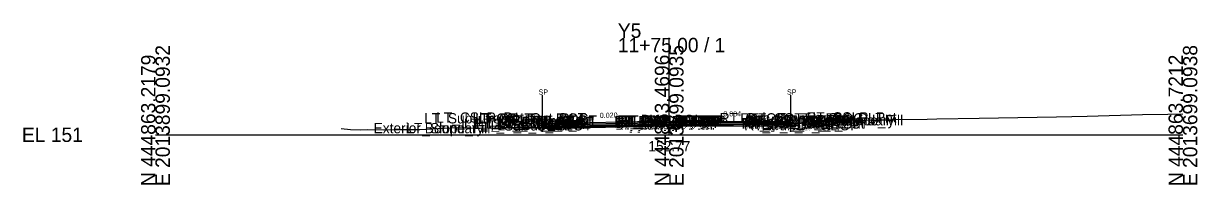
# Model space of a CAD drawing. Extents: x -26 to 203, y -10 to 4517.
# Drawn here: x -25.7 to 202.8, y 3490.3 to 3521.7 of the extents above; entities that cross this region are included whole.
import ezdxf

# ---------------------------------------------------------------- set-up
doc = ezdxf.new("R2010")
doc.units = 0
for name, color, linetype in [('Default', 7, 'Continuous'), ('Exist Cross Section Cell', 7, 'Continuous'), ('Exist XS Center Line Elevation Label', 7, 'Continuous'), ('Exist XS Ground Line', 7, 'Continuous'), ('Prop CMT Pvmt Course 1', 7, 'Continuous'), ('Prop CMT Pvmt Course 1 CG', 7, 'Continuous'), ('Prop CMT Pvmt Course 2', 7, 'Continuous'), ('Prop CMT Pvmt Course 3', 7, 'Continuous'), ('Prop CMT Pvmt Surface', 7, 'Continuous'), ('Prop CMT Shear Line', 7, 'Continuous'), ('Prop CMT Subgrade Earthwork', 7, 'Continuous'), ('Prop XS Earthwork Shape', 7, 'Continuous'), ('Prop XS SE Text', 7, 'Continuous'), ('Scratch_Level_0', 7, 'Continuous')]:
    doc.layers.add(name, color=color, linetype=linetype)

msp = doc.modelspace()

# ---------------------------------------------------------------- linework, layer by layer
at = {"layer": 'Exist Cross Section Cell'}
for p, q in [((100, 3500), (100, 3518.88)), ((0, 3500), (100, 3500)), ((100, 3500), (200, 3500))]:
    msp.add_line(p, q, dxfattribs=at)
at = {"layer": 'Exist XS Ground Line'}
msp.add_lwpolyline([(36.17, 3501.2), (37.98, 3501.05), (39.97, 3500.97), (41.27, 3501.01), (44.37, 3500.99), (46.75, 3501), (48.12, 3501.01), (49.51, 3501), (51.44, 3501.02), (58.5, 3501.4), (61.38, 3501.35), (66.68, 3501.26), (67.48, 3501.42), (71.17, 3501.42), (75.28, 3501.48), (78.99, 3501.4), (79.51, 3501.41), (86.8, 3501.57), (88.02, 3501.77), (89.34, 3501.63), (90.83, 3501.65), (100, 3501.77), (100.85, 3501.78), (101.99, 3501.79), (116.01, 3502.09), (123.64, 3502.22), (125.03, 3502.24), (125.61, 3502.24), (126.49, 3502.63), (127.48, 3502.69), (128.73, 3502.67), (131.38, 3502.66), (140.74, 3502.91), (142.43, 3502.94), (143.15, 3502.95), (150.2, 3503.07), (152.09, 3503.1), (160.32, 3503.25), (175.39, 3503.52), (181.39, 3503.63), (192.16, 3503.96), (197.08, 3504.03), (200, 3504.05)], dxfattribs=at)
at = {"layer": 'Prop CMT Pvmt Course 1'}
for points in [[(100, 3502.63), (75.24, 3502.14)], [(75.24, 3502.49), (75.24, 3502.24)], [(75.24, 3501.89), (100, 3502.38)], [(100, 3502.38), (100, 3502.63)], [(100, 3502.63), (123.6, 3502.58)], [(100, 3502.38), (100, 3502.63)], [(123.6, 3502.33), (100, 3502.38)]]:
    msp.add_lwpolyline(points, dxfattribs=at)
msp.add_lwpolyline([(100, 3502.38), (100, 3502.51), (100, 3502.51), (100, 3502.38)], close=True, dxfattribs=at)
msp.add_lwpolyline([(100, 3502.38), (100, 3502.51), (100, 3502.51), (100, 3502.38)], close=True, dxfattribs=at)
at = {"layer": 'Prop CMT Pvmt Course 1 CG'}
msp.add_lwpolyline([(75.24, 3501.58), (75.24, 3501.91)], dxfattribs=at)
at = {"layer": 'Prop CMT Pvmt Course 2'}
for points in [[(100, 3502.38), (75.24, 3501.89)], [(75.24, 3502.24), (75.24, 3501.91)], [(75.24, 3501.56), (100, 3502.05)], [(100, 3502.05), (100, 3502.38)], [(100, 3502.05), (100, 3502.38)], [(100, 3502.38), (123.6, 3502.33)], [(123.6, 3501.99), (100, 3502.05)]]:
    msp.add_lwpolyline(points, dxfattribs=at)
at = {"layer": 'Prop CMT Pvmt Course 3'}
for points in [[(100, 3502.05), (75.24, 3501.56)], [(75.24, 3501.91), (75.24, 3501.58)], [(75.24, 3501.22), (100, 3501.72)], [(100, 3501.72), (100, 3502.05)], [(100, 3502.05), (123.6, 3501.99)], [(100, 3501.72), (100, 3502.05)], [(123.6, 3501.66), (100, 3501.72)]]:
    msp.add_lwpolyline(points, dxfattribs=at)
at = {"layer": 'Prop CMT Pvmt Surface'}
for points in [[(100, 3502.63), (75.24, 3502.14)], [(100, 3502.63), (123.6, 3502.58)]]:
    msp.add_lwpolyline(points, dxfattribs=at)
at = {"layer": 'Prop CMT Shear Line'}
for p, q in [((75.24, 3507.71), (75.24, 3500.57)), ((123.6, 3507.71), (123.6, 3500.57))]:
    msp.add_line(p, q, dxfattribs=at)
at = {"layer": 'Prop CMT Subgrade Earthwork'}
for p, q in [((75.24, 3501.47), (75.24, 3501.22)), ((123.6, 3501.66), (123.6, 3502.22))]:
    msp.add_line(p, q, dxfattribs=at)
for points in [[(100, 3501.72), (75.24, 3501.22)], [(100, 3501.72), (123.6, 3501.66)]]:
    msp.add_lwpolyline(points, dxfattribs=at)
at = {"layer": 'Prop XS Earthwork Shape'}
msp.add_lwpolyline([(75.24, 3501.47), (75.24, 3501.22), (100, 3501.72), (123.6, 3501.66), (123.6, 3502.22), (116.01, 3502.09), (101.99, 3501.79), (100.85, 3501.78), (100, 3501.77), (90.83, 3501.65), (89.34, 3501.63), (88.02, 3501.77), (86.8, 3501.57), (79.51, 3501.41), (78.99, 3501.4), (75.28, 3501.48)], close=True, dxfattribs=at)

# ---------------------------------------------------------------- texts
at = {"layer": 'Default'}
msp.add_text('-', height=0.0001, dxfattribs=at).set_placement((0, 3500))
at = {"layer": 'Exist Cross Section Cell'}
for s, p in [('Y5', (90, 3518.88)), ('11+75.00 / 1', (90, 3516.08)), ('EL 151', (-26, 3498.6))]:
    msp.add_text(s, height=2.8, dxfattribs=at).set_placement(p)
for s, p in [('E 2013899.0932', (2.8, 3490)), ('E 2013799.0935', (102.8, 3490)), ('E 2013699.0938', (202.8, 3490)), ('N 444863.2179', (0, 3490)), ('N 444863.4696', (100, 3490)), ('N 444863.7212', (200, 3490))]:
    msp.add_text(s, height=2.8, rotation=90, dxfattribs=at).set_placement(p)
at = {"layer": 'Exist XS Center Line Elevation Label'}
msp.add_text('152.77', height=2, dxfattribs=at).set_placement((95.94, 3496.77))
at = {"layer": 'Prop XS SE Text'}
for s, rotation, p in [('SP', 360, (74.57, 3507.83)), ('SP', 360, (122.92, 3507.83)), ('0.020', 1.1458, (86.5, 3503.27)), ('0.004', 359.7512, (110.53, 3503.59))]:
    msp.add_text(s, height=1, rotation=rotation, dxfattribs=at).set_placement(p)
at = {"layer": 'Scratch_Level_0'}
for s, p in [('LT_Sub_Trench_Out_DLT', (52.31, 3502.21)), ('LT_CSLP_Pnt', (54.64, 3502.36)), ('LT_CG_Top_Face', (61.73, 3502.17)), ('LT_CG_Top_BOC', (62.25, 3502.17)), ('LT_CG_Top_Gut', (62.71, 3501.67)), ('LT_PV2_OEOT', (66.64, 3501.51)), ('LT_PV1_OEOT', (67.21, 3501.76)), ('RT_PV2_OEEOP', (89.3, 3501.64)), ('LT_PV2_OEEOP', (89.35, 3501.64)), ('RT_PV1_OEEOP', (89.87, 3501.77)), ('LT_PV1_OEEOP', (89.92, 3501.77)), ('RT_PV2_IEEOP', (89.95, 3501.64)), ('LT_PV2_IEEOP', (89.99, 3501.64)), ('RT_PV1_IEEOP', (90.51, 3501.77)), ('LT_PV1_IEEOP', (90.56, 3501.77)), ('PV2_PGL', (93.95, 3501.64)), ('PV1_PGL', (94.51, 3501.89)), ('RT_Sub_Trench_Out_DLT', (109.83, 3502.24)), ('RT_CG_Top_Face', (113.8, 3502.2)), ('RT_PV2_OEOT', (114.71, 3501.54)), ('RT_CG_Top_Gut', (114.78, 3501.7)), ('RT_PV1_OEOT', (115.28, 3501.79)), ('RT_CG_Top_BOC', (115.33, 3502.2)), ('Exterior Boundary', (122.41, 3501.83)), ('RT_CSLP_Pnt', (126.72, 3502.39)), ('RT_Slope_Fill', (128.74, 3501.83)), ('Exterior Boundary', (42.46, 3500.29)), ('LT_Slope_Fill', (48.83, 3500.29)), ('LT_CG1_Shelf_Out', (60.02, 3501.16)), ('LT_CG_Bot_BOC', (62.29, 3501.16)), ('LT_Sub_OEOP', (63.25, 3500.82)), ('LT_CG_Bot_IE', (66.38, 3501.18)), ('LT_Sub_OEOT', (66.55, 3500.84)), ('LT_PV3_OEOT', (66.64, 3501.18)), ('RT_Sub_OEEOP', (89.21, 3500.98)), ('LT_Sub_OEEOP', (89.25, 3500.98)), ('RT_PV3_OEEOP', (89.3, 3501.31)), ('LT_PV3_OEEOP', (89.35, 3501.31)), ('RT_CG1_Shelf_Out', (114.09, 3501.19)), ('RT_CG_Bot_IE', (114.45, 3501.2)), ('RT_Sub_OEOT', (114.62, 3500.87)), ('RT_PV3_OEOT', (114.71, 3501.2)), ('RT_CG_Bot_BOC', (115.36, 3501.19)), ('RT_Sub_OEOP', (117.99, 3500.86))]:
    msp.add_text(s, height=2, dxfattribs=at).set_placement(p)

doc.saveas('drawing.dxf')
